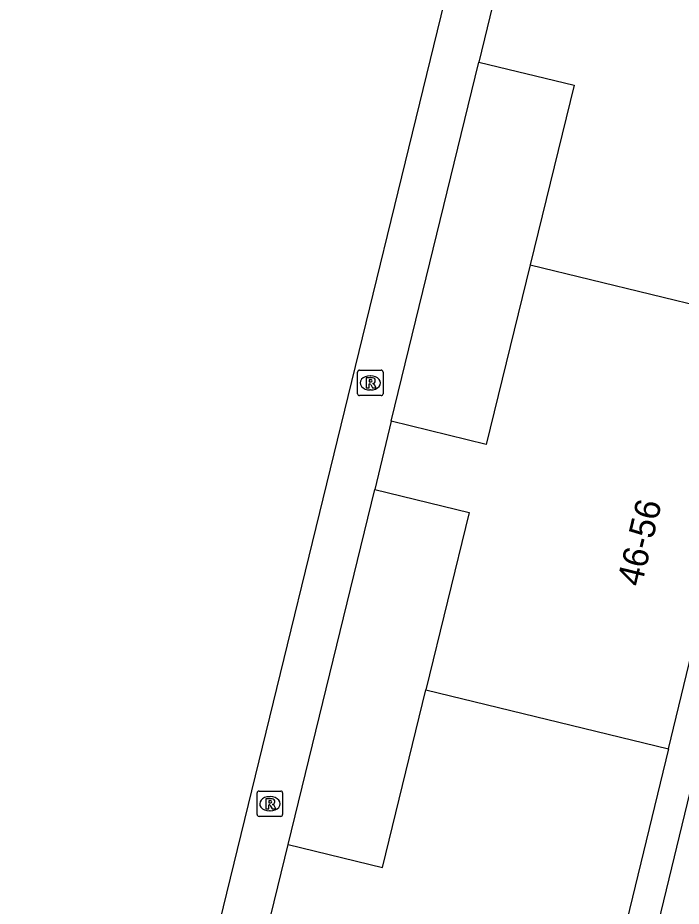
# Model space of a CAD drawing. Extents: x 162812 to 163818, y 381639 to 382470.
# Drawn here: x 163052.51 to 163078.62, y 382258.67 to 382293.63 of the extents above; entities that cross this region are included whole.
import ezdxf

# ---------------------------------------------------------------- set-up
doc = ezdxf.new("R2010")
doc.units = 0
for name, color, linetype in [('IMGEO_Pand', 7, 'Continuous'), ('IMGEO_Pand_nummerreeks', 7, 'Continuous'), ('IMGEO_Rioolput', 7, 'Continuous'), ('IMGEO_Voetpad_open', 7, 'Continuous')]:
    doc.layers.add(name, color=color, linetype=linetype)

msp = doc.modelspace()

# ---------------------------------------------------------------- linework, layer by layer
at = {"layer": 'IMGEO_Pand'}
for points in [[(163071.315, 382294.597), (163070.655, 382291.891)], [(163070.655, 382291.891), (163074.4, 382290.976), (163072.673, 382283.908)], [(163072.673, 382283.908), (163070.947, 382276.84), (163067.21, 382277.754)], [(163072.673, 382283.908), (163082.175, 382281.603)], [(163078.114, 382264.863), (163082.175, 382281.603)], [(163067.21, 382277.754), (163066.557, 382275.073)], [(163066.557, 382275.073), (163070.273, 382274.165), (163068.567, 382267.18)], [(163063.152, 382261.102), (163066.861, 382260.195), (163068.567, 382267.18)], [(163068.567, 382267.18), (163078.114, 382264.863)], [(163078.114, 382264.863), (163074.508, 382250), (163073.948, 382247.695)], [(163062.469, 382258.3), (163063.152, 382261.102)]]:
    msp.add_lwpolyline(points, dxfattribs=at)
at = {"layer": 'IMGEO_Rioolput'}
for p, q in [((163065.883, 382278.838), (163065.883, 382279.69)), ((163065.958, 382279.764), (163066.81, 382279.764)), ((163066.884, 382279.69), (163066.884, 382278.838)), ((163066.371, 382279.544), (163066.396, 382279.544)), ((163066.394, 382278.984), (163066.369, 382278.984)), ((163066.81, 382278.764), (163065.958, 382278.764)), ((163062.004, 382263.2), (163062.856, 382263.2)), ((163061.929, 382262.274), (163061.929, 382263.126)), ((163062.417, 382262.98), (163062.442, 382262.98)), ((163062.93, 382263.126), (163062.93, 382262.274)), ((163062.856, 382262.2), (163062.004, 382262.2)), ((163062.44, 382262.42), (163062.415, 382262.42))]:
    msp.add_line(p, q, dxfattribs=at)
for points in [[(163065.883, 382278.838), (163065.883, 382279.69)], [(163065.958, 382279.764), (163066.81, 382279.764)], [(163066.884, 382279.69), (163066.884, 382278.838)], [(163066.472, 382279.462), (163066.22, 382279.464), (163066.22, 382279.064)], [(163066.22, 382279.064), (163066.344, 382279.064), (163066.344, 382279.226), (163066.355, 382279.226)], [(163066.398, 382279.383), (163066.344, 382279.383), (163066.344, 382279.302)], [(163066.344, 382279.302), (163066.396, 382279.302)], [(163066.402, 382279.197), (163066.473, 382279.064), (163066.613, 382279.064), (163066.548, 382279.19)], [(163066.81, 382278.764), (163065.958, 382278.764)], [(163062.004, 382263.2), (163062.856, 382263.2)], [(163061.929, 382262.274), (163061.929, 382263.126)], [(163062.518, 382262.898), (163062.266, 382262.9), (163062.266, 382262.5)], [(163062.444, 382262.819), (163062.39, 382262.819), (163062.39, 382262.738)], [(163062.93, 382263.126), (163062.93, 382262.274)], [(163062.266, 382262.5), (163062.39, 382262.5), (163062.39, 382262.662), (163062.401, 382262.662)], [(163062.39, 382262.738), (163062.442, 382262.738)], [(163062.448, 382262.633), (163062.519, 382262.5), (163062.659, 382262.5), (163062.594, 382262.626)], [(163062.856, 382262.2), (163062.004, 382262.2)]]:
    msp.add_lwpolyline(points, dxfattribs=at)
for centre, radius, start, end in [((163065.96, 382279.688), 0.0765, 91.552, 178.448), ((163065.96, 382279.688), 0.0765, 91.552, 178.448), ((163066.808, 382279.688), 0.0765, 1.552, 88.448), ((163066.808, 382279.688), 0.0765, 1.552, 88.448), ((163066.354, 382279.173), 0.0533, 26.0293, 88.6989), ((163066.38, 382279.491), 0.19, 274.7715, 282.9687), ((163066.404, 382279.287), 0.0964, 77.0061, 93.1865), ((163066.418, 382279.344), 0.0378, 276.6634, 79.6772), ((163066.471, 382279.352), 0.109, 350.3612, 89.416), ((163066.469, 382279.352), 0.112, 277.5842, 350.9817), ((163066.453, 382279.137), 0.108, 29.5134, 73.7905), ((163065.96, 382278.84), 0.0765, 181.552, 268.448), ((163065.96, 382278.84), 0.0765, 181.552, 268.448), ((163066.808, 382278.84), 0.0765, 271.552, 358.448), ((163066.808, 382278.84), 0.0765, 271.552, 358.448), ((163062.006, 382263.124), 0.0765, 91.552, 178.448), ((163062.006, 382263.124), 0.0765, 91.552, 178.448), ((163062.854, 382263.124), 0.0765, 1.552, 88.448), ((163062.854, 382263.124), 0.0765, 1.552, 88.448), ((163062.45, 382262.723), 0.0964, 77.0061, 93.1865), ((163062.464, 382262.78), 0.0378, 276.6634, 79.6772), ((163062.517, 382262.788), 0.109, 350.3612, 89.416), ((163062.4, 382262.609), 0.0533, 26.0293, 88.6989), ((163062.426, 382262.927), 0.19, 274.7715, 282.9687), ((163062.515, 382262.788), 0.112, 277.5842, 350.9817), ((163062.499, 382262.573), 0.108, 29.5134, 73.7905), ((163062.006, 382262.276), 0.0765, 181.552, 268.448), ((163062.006, 382262.276), 0.0765, 181.552, 268.448), ((163062.854, 382262.276), 0.0765, 271.552, 358.448), ((163062.854, 382262.276), 0.0765, 271.552, 358.448)]:
    msp.add_arc(centre, radius, start, end, dxfattribs=at)
for centre, major_axis, ratio, start_param, end_param in [((163066.37, 382279.264), (-0.387, 0.002), 0.722429, 4.712389, 7.853982), ((163066.395, 382279.264), (-0.39, 0.002), 0.717154, 1.570796, 4.712389), ((163062.416, 382262.7), (-0.387, 0.002), 0.722429, 4.712389, 7.853982), ((163062.441, 382262.7), (-0.39, 0.002), 0.717154, 1.570796, 4.712389)]:
    msp.add_ellipse(centre, major_axis=major_axis, ratio=ratio, start_param=start_param, end_param=end_param, dxfattribs=at)
at = {"layer": 'IMGEO_Voetpad_open'}
for points in [[(163071.966, 382305.208), (163058.483, 382250), (163052.509, 382225.538), (163054.451, 382225.06)], [(163087.242, 382301.595), (163086.447, 382298.575), (163087.465, 382298.318), (163075.774, 382250), (163067.591, 382216.313), (163067.07, 382214.116)], [(163067.21, 382277.754), (163070.655, 382291.891)], [(163063.152, 382261.102), (163066.557, 382275.073)]]:
    msp.add_lwpolyline(points, dxfattribs=at)

# ---------------------------------------------------------------- texts
at = {"layer": 'IMGEO_Pand_nummerreeks'}
msp.add_text('46-56', height=1, rotation=76.373, dxfattribs=at).set_placement((163077.05, 382271.209))

doc.saveas('drawing.dxf')
